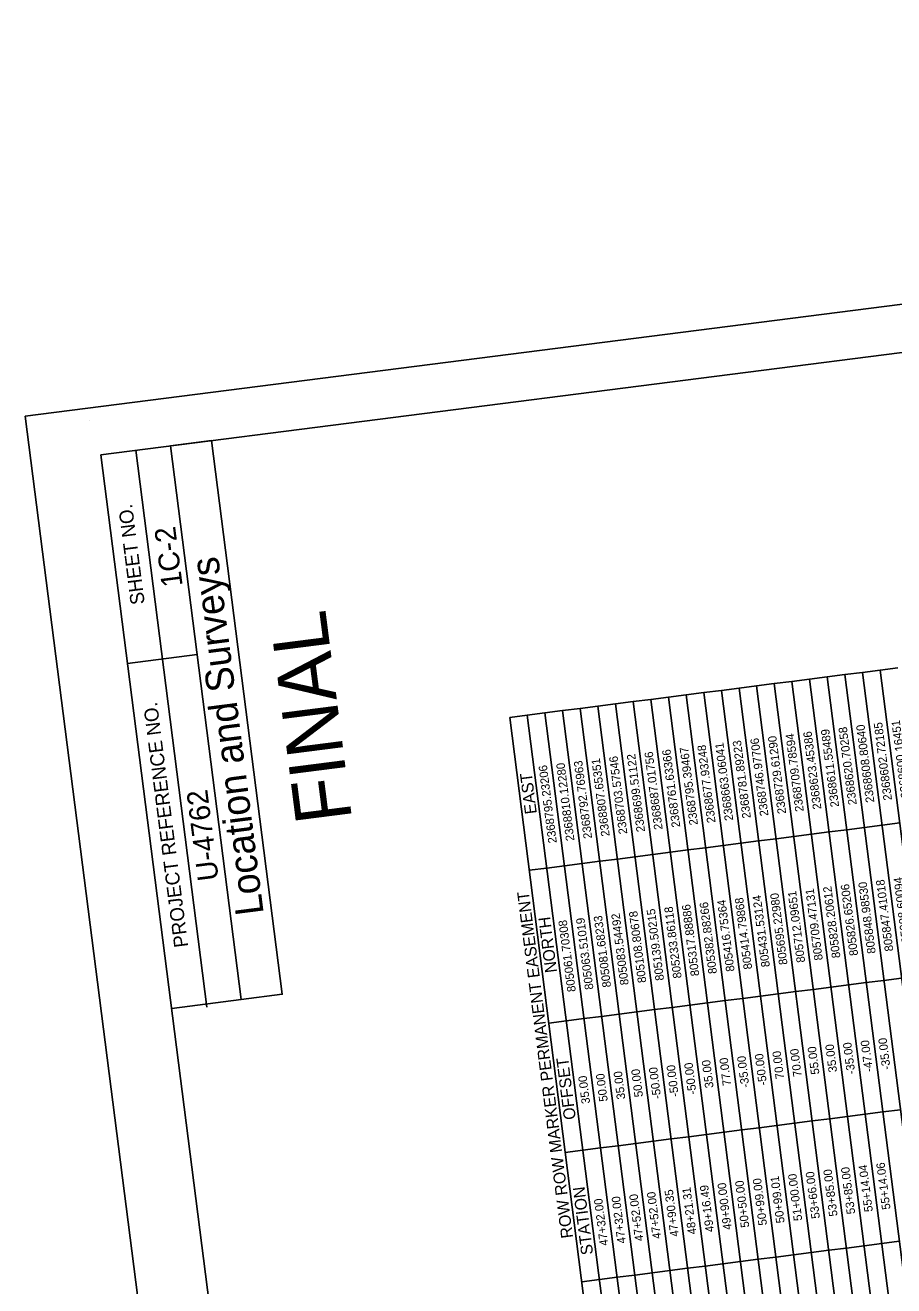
# Model space of a CAD drawing. Extents: x 2364621 to 2374814, y 792603 to 806745.
# Drawn here: x 2364621 to 2367039, y 803235 to 806745 of the extents above; entities that cross this region are included whole.
import ezdxf

# ---------------------------------------------------------------- set-up
doc = ezdxf.new("R2010")
doc.units = 0
for name, color, linetype in [('CTL Sheet Border CELL', 7, 'Continuous'), ('CTL Sheet Notes CELL', 7, 'Continuous'), ('CTL Sheet Table Cell', 7, 'Continuous'), ('CTL Sheet Text', 7, 'Continuous'), ('Default', 7, 'Continuous'), ('Scratch_Level_0', 7, 'Continuous')]:
    doc.layers.add(name, color=color, linetype=linetype)

msp = doc.modelspace()

# ---------------------------------------------------------------- linework, layer by layer
at = {"layer": 'CTL Sheet Border CELL'}
for p, q in [((2364620.8, 805656.2), (2364620.8, 805656.2)), ((2364799.1, 805643.5), (2364799.1, 805643.5)), ((2364799.1, 805643.5), (2364799.1, 805643.5)), ((2365126.7, 804010.9), (2364928.6, 805561.6)), ((2364905.9, 804967.9), (2365099.7, 804992.6)), ((2365028.6, 804007.3), (2365222.4, 804032))]:
    msp.add_line(p, q, dxfattribs=at)
for points in [[(2364831.4, 805549.1), (2366316.3, 793922.1), (2374455.2, 794961.6), (2372970.2, 806588.6)], [(2365222.4, 804032), (2365025.5, 805573.9), (2365139.6, 805588.5), (2365336.5, 804046.6)]]:
    msp.add_lwpolyline(points, close=True, dxfattribs=at)
at = {"layer": 'CTL Sheet Table Cell'}
for p, q in [((2366804.5, 804924.1), (2366853.6, 804930.4)), ((2366853.6, 804930.4), (2366902.7, 804936.7)), ((2367087.8, 803096.7), (2366853.6, 804930.4)), ((2366902.7, 804936.7), (2366951.8, 804943)), ((2367136.9, 803102.9), (2366902.7, 804936.7)), ((2366951.8, 804943), (2367000.9, 804949.2)), ((2367186, 803109.2), (2366951.8, 804943)), ((2367000.9, 804949.2), (2367050, 804955.5)), ((2367235.1, 803115.5), (2367000.9, 804949.2)), ((2366509.7, 804886.5), (2366558.9, 804892.8)), ((2366558.9, 804892.8), (2366608, 804899)), ((2366793.1, 803059), (2366558.9, 804892.8)), ((2366608, 804899), (2366657.1, 804905.3)), ((2366842.2, 803065.3), (2366608, 804899)), ((2366657.1, 804905.3), (2366706.2, 804911.6)), ((2366891.3, 803071.6), (2366657.1, 804905.3)), ((2366706.2, 804911.6), (2366755.3, 804917.9)), ((2366940.4, 803077.9), (2366706.2, 804911.6)), ((2366755.3, 804917.9), (2366804.5, 804924.1)), ((2366989.5, 803084.1), (2366755.3, 804917.9)), ((2367038.7, 803090.4), (2366804.5, 804924.1)), ((2366264.2, 804855.1), (2366313.3, 804861.4)), ((2366313.3, 804861.4), (2366362.4, 804867.7)), ((2366547.5, 803027.7), (2366313.3, 804861.4)), ((2366362.4, 804867.7), (2366411.5, 804874)), ((2366596.6, 803033.9), (2366362.4, 804867.7)), ((2366411.5, 804874), (2366460.6, 804880.2)), ((2366645.7, 803040.2), (2366411.5, 804874)), ((2366460.6, 804880.2), (2366509.7, 804886.5)), ((2366694.8, 803046.5), (2366460.6, 804880.2)), ((2366744, 803052.8), (2366509.7, 804886.5)), ((2365969.5, 804817.5), (2366018.6, 804823.8)), ((2366018.6, 804823.8), (2366067.7, 804830)), ((2366252.8, 802990), (2366018.6, 804823.8)), ((2366067.7, 804830), (2366116.8, 804836.3)), ((2366301.9, 802996.3), (2366067.7, 804830)), ((2366116.8, 804836.3), (2366165.9, 804842.6)), ((2366351, 803002.6), (2366116.8, 804836.3)), ((2366165.9, 804842.6), (2366215, 804848.9)), ((2366400.1, 803008.8), (2366165.9, 804842.6)), ((2366215, 804848.9), (2366264.2, 804855.1)), ((2366449.2, 803015.1), (2366215, 804848.9)), ((2366498.4, 803021.4), (2366264.2, 804855.1)), ((2366203.7, 802983.8), (2365969.5, 804817.5)), ((2366907.9, 804504.7), (2366957.1, 804511)), ((2366957.1, 804511), (2367006.2, 804517.3)), ((2367006.2, 804517.3), (2367055.3, 804523.5)), ((2366613.2, 804467.1), (2366662.4, 804473.4)), ((2366662.4, 804473.4), (2366711.5, 804479.6)), ((2366711.5, 804479.6), (2366760.6, 804485.9)), ((2366760.6, 804485.9), (2366809.7, 804492.2)), ((2366809.7, 804492.2), (2366858.8, 804498.4)), ((2366858.8, 804498.4), (2366907.9, 804504.7)), ((2366367.6, 804435.7), (2366416.8, 804442)), ((2366416.8, 804442), (2366465.9, 804448.3)), ((2366465.9, 804448.3), (2366515, 804454.5)), ((2366515, 804454.5), (2366564.1, 804460.8)), ((2366564.1, 804460.8), (2366613.2, 804467.1)), ((2366072.9, 804398.1), (2366122.1, 804404.3)), ((2366122.1, 804404.3), (2366171.2, 804410.6)), ((2366171.2, 804410.6), (2366220.3, 804416.9)), ((2366220.3, 804416.9), (2366269.4, 804423.2)), ((2366269.4, 804423.2), (2366318.5, 804429.4)), ((2366318.5, 804429.4), (2366367.6, 804435.7)), ((2366023.8, 804391.8), (2366072.9, 804398.1)), ((2366962.3, 804079), (2367011.4, 804085.3)), ((2367011.4, 804085.3), (2367060.5, 804091.6)), ((2366716.7, 804047.7), (2366765.8, 804053.9)), ((2366765.8, 804053.9), (2366815, 804060.2)), ((2366815, 804060.2), (2366864.1, 804066.5)), ((2366864.1, 804066.5), (2366913.2, 804072.8)), ((2366913.2, 804072.8), (2366962.3, 804079)), ((2366422, 804010), (2366471.1, 804016.3)), ((2366471.1, 804016.3), (2366520.2, 804022.6)), ((2366520.2, 804022.6), (2366569.4, 804028.8)), ((2366569.4, 804028.8), (2366618.5, 804035.1)), ((2366618.5, 804035.1), (2366667.6, 804041.4)), ((2366667.6, 804041.4), (2366716.7, 804047.7)), ((2366176.4, 803978.7), (2366225.5, 803984.9)), ((2366225.5, 803984.9), (2366274.7, 803991.2)), ((2366274.7, 803991.2), (2366323.8, 803997.5)), ((2366323.8, 803997.5), (2366372.9, 804003.8)), ((2366372.9, 804003.8), (2366422, 804010)), ((2366078.2, 803966.1), (2366127.3, 803972.4)), ((2366127.3, 803972.4), (2366176.4, 803978.7)), ((2366811.8, 803693.7), (2366861, 803700)), ((2366861, 803700), (2366910.1, 803706.3)), ((2366910.1, 803706.3), (2366959.2, 803712.6)), ((2366959.2, 803712.6), (2367008.3, 803718.8)), ((2367008.3, 803718.8), (2367057.4, 803725.1)), ((2366566.3, 803662.4), (2366615.4, 803668.6)), ((2366615.4, 803668.6), (2366664.5, 803674.9)), ((2366664.5, 803674.9), (2366713.6, 803681.2)), ((2366713.6, 803681.2), (2366762.7, 803687.5)), ((2366762.7, 803687.5), (2366811.8, 803693.7)), ((2366271.5, 803624.7), (2366320.7, 803631)), ((2366320.7, 803631), (2366369.8, 803637.3)), ((2366369.8, 803637.3), (2366418.9, 803643.6)), ((2366418.9, 803643.6), (2366468, 803649.8)), ((2366468, 803649.8), (2366517.1, 803656.1)), ((2366517.1, 803656.1), (2366566.3, 803662.4)), ((2366124.2, 803605.9), (2366173.3, 803612.2)), ((2366173.3, 803612.2), (2366222.4, 803618.5)), ((2366222.4, 803618.5), (2366271.5, 803624.7)), ((2366956.1, 803346.1), (2367005.2, 803352.4)), ((2367005.2, 803352.4), (2367054.3, 803358.6)), ((2366661.4, 803308.5), (2366710.5, 803314.7)), ((2366710.5, 803314.7), (2366759.6, 803321)), ((2366759.6, 803321), (2366808.7, 803327.3)), ((2366808.7, 803327.3), (2366857.8, 803333.5)), ((2366857.8, 803333.5), (2366907, 803339.8)), ((2366907, 803339.8), (2366956.1, 803346.1)), ((2366415.8, 803277.1), (2366464.9, 803283.4)), ((2366464.9, 803283.4), (2366514, 803289.6)), ((2366514, 803289.6), (2366563.1, 803295.9)), ((2366563.1, 803295.9), (2366612.3, 803302.2)), ((2366612.3, 803302.2), (2366661.4, 803308.5)), ((2366170.2, 803245.7), (2366219.3, 803252)), ((2366219.3, 803252), (2366268.4, 803258.3)), ((2366268.4, 803258.3), (2366317.6, 803264.5)), ((2366317.6, 803264.5), (2366366.7, 803270.8)), ((2366366.7, 803270.8), (2366415.8, 803277.1))]:
    msp.add_line(p, q, dxfattribs=at)
at = {"layer": 'Scratch_Level_0'}
msp.add_lwpolyline([(2374814.3, 793692), (2373147.1, 806745.2), (2364620.8, 805656.2), (2366287.9, 792603)], close=True, dxfattribs=at)

# ---------------------------------------------------------------- texts
at = {"layer": 'CTL Sheet Border CELL'}
for s, height, p in [('SHEET NO.', 39.07, (2364953.7, 805134)), ('Location and Surveys', 78.144, (2365285, 804271.3)), ('FINAL', 156.29, (2365531, 804533.3)), ('PROJECT REFERENCE NO.', 39.072, (2365074.8, 804179.3))]:
    msp.add_text(s, height=height, rotation=97.2784, dxfattribs=at).set_placement(p)
at = {"layer": 'CTL Sheet Notes CELL'}
for s, height, p in [('EAST', 33.01, (2366045.2, 804550.3)), ('ROW ROW MARKER PERMANENT EASEMENT', 33.011, (2366146.1, 803369)), ('NORTH', 33.01, (2366101.6, 804108.4)), ('OFFSET', 33.01, (2366153.9, 803699.2)), ('STATION', 33.01, (2366202, 803322.8))]:
    msp.add_text(s, height=height, rotation=97.2784, dxfattribs=at).set_placement(p)
at = {"layer": 'CTL Sheet Text'}
for s, height, p in [('2368620.70258', 23.579, (2366935.8, 804575.2)), ('2368608.80640', 23.579, (2366984.9, 804581.5)), ('2368602.72185', 23.579, (2367034, 804587.8)), ('2368600.16451', 23.579, (2367083.1, 804594)), ('2368781.89223', 23.579, (2366641.1, 804537.6)), ('2368746.97706', 23.579, (2366690.2, 804543.9)), ('2368729.61290', 23.579, (2366739.3, 804550.1)), ('2368709.78594', 23.579, (2366788.4, 804556.4)), ('2368623.45386', 23.579, (2366837.5, 804562.7)), ('2368611.55489', 23.579, (2366886.7, 804569)), ('2368687.01756', 23.579, (2366395.5, 804506.2)), ('2368761.63366', 23.579, (2366444.6, 804512.5)), ('2368795.39467', 23.579, (2366493.7, 804518.8)), ('2368677.93248', 23.579, (2366542.8, 804525)), ('2368663.06041', 23.579, (2366592, 804531.3)), ('2368795.23206', 23.579, (2366100.8, 804468.6)), ('2368810.12280', 23.579, (2366149.9, 804474.9)), ('2368792.76963', 23.579, (2366199, 804481.1)), ('2368807.65351', 23.579, (2366248.1, 804487.4)), ('2368703.57546', 23.579, (2366297.2, 804493.7)), ('2368699.51122', 23.579, (2366346.4, 804500)), ('805908.60094', 23.579, (2367086.9, 804173.7)), ('805712.09651', 23.579, (2366792.2, 804136.1)), ('805709.47131', 23.579, (2366841.3, 804142.3)), ('805828.20612', 23.579, (2366890.4, 804148.6)), ('805826.65206', 23.579, (2366939.6, 804154.9)), ('805848.98530', 23.579, (2366988.7, 804161.1)), ('805847.41018', 23.579, (2367037.8, 804167.4)), ('805317.88886', 23.579, (2366497.5, 804098.4)), ('805382.88266', 23.579, (2366546.6, 804104.7)), ('805416.75364', 23.579, (2366595.7, 804111)), ('805414.79868', 23.579, (2366644.8, 804117.2)), ('805431.53124', 23.579, (2366694, 804123.5)), ('805695.22980', 23.579, (2366743.1, 804129.8)), ('805081.68233', 23.579, (2366251.9, 804067)), ('805083.54492', 23.579, (2366301, 804073.3)), ('805108.80678', 23.579, (2366350.1, 804079.6)), ('805139.50215', 23.579, (2366399.3, 804085.9)), ('805233.86118', 23.579, (2366448.4, 804092.1)), ('805061.70308', 23.579, (2366153.7, 804054.5)), ('805063.51019', 23.579, (2366202.8, 804060.8)), ('-35.00', 23.58, (2366931.7, 803825.3)), ('-47.00', 23.58, (2366980.8, 803831.5)), ('-35.00', 23.58, (2367030, 803837.8)), ('-50.00', 23.58, (2366686.1, 803793.9)), ('70.00', 23.58, (2366733.8, 803811.8)), ('70.00', 23.58, (2366782.9, 803818.1)), ('55.00', 23.58, (2366832, 803824.3)), ('35.00', 23.58, (2366881.1, 803830.6)), ('-50.00', 23.58, (2366391.4, 803756.3)), ('-50.00', 23.58, (2366440.5, 803762.5)), ('-50.00', 23.58, (2366489.7, 803768.8)), ('35.00', 23.58, (2366537.3, 803786.7)), ('77.00', 23.58, (2366586.4, 803793)), ('-35.00', 23.58, (2366637, 803787.6)), ('35.00', 23.58, (2366193.5, 803742.8)), ('50.00', 23.58, (2366242.6, 803749)), ('35.00', 23.58, (2366291.7, 803755.3)), ('50.00', 23.58, (2366340.8, 803761.6)), ('53+85.00', 23.58, (2366882.5, 803429.3)), ('53+85.00', 23.58, (2366931.6, 803435.6)), ('55+14.04', 23.58, (2366980.7, 803441.9)), ('55+14.06', 23.58, (2367029.8, 803448.1)), ('50+50.00', 23.58, (2366636.9, 803398)), ('50+99.00', 23.58, (2366686, 803404.2)), ('50+99.01', 23.58, (2366735.1, 803410.5)), ('51+00.00', 23.58, (2366784.2, 803416.8)), ('53+66.00', 23.58, (2366833.3, 803423)), ('47+52.00', 23.58, (2366342.2, 803360.3)), ('47+52.00', 23.58, (2366391.3, 803366.6)), ('47+90.35', 23.58, (2366440.4, 803372.9)), ('48+21.31', 23.58, (2366489.5, 803379.1)), ('49+16.49', 23.58, (2366538.6, 803385.4)), ('49+90.00', 23.58, (2366587.8, 803391.7)), ('47+32.00', 23.58, (2366243.9, 803347.8)), ('47+32.00', 23.58, (2366293, 803354))]:
    msp.add_text(s, height=height, rotation=97.2784, dxfattribs=at).set_placement(p)
at = {"layer": 'Default'}
for s, p in [('1C-2', (2365059.2, 805184.3)), ('U-4762', (2365159.6, 804365.9))]:
    msp.add_text(s, height=58.22, rotation=97.2784, dxfattribs=at).set_placement(p)

doc.saveas('drawing.dxf')
